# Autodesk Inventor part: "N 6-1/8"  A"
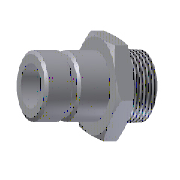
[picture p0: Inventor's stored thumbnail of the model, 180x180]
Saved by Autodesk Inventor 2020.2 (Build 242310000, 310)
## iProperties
IsCustomPart: 1
Manager: www.cadconsulting.pl
Company: Fabian Stasiak CAD Consulting
Created: 2014-02
Part Number: "N 6-1/8"  A"
Material: Copper,Cu
Description: Connector Plug
Document SubType Name: Modeling
Designer: F.Stasiak
Standard Revision: 1
Manufacturer: DME
Language: pl-PL
Size Designation: "N 6-1/8"  A"
Categories: <MemberInstance><Categories><Category DisplayName="Forma wtryskowa" InternalName="349578f2-f4d4-4954-8c09-8e99297a61c0" Mnemonic="MOLD"><Category DisplayName="K
Mass: 1.2815 g
Surface Area: 14.3289 cm^2
Volume: 1.2815 cm^3
Density: 8.96 g/cm^3
Appearance: Domyślne
Catalog Web Link: www.expertbooks.pl
Author: F.Stasiak
Subject: Zbiór ćwiczeń. Autodesk Inventor 2020. Kurs Professional
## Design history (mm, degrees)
sketch "Sketch1"
  geometry: L1 (0, -8.77)-(0, 24.83) reference; L2 (36.525, 1.418)-(37.025, 17.418); L3 (37.025, 17.418)-(36.525, 17.418); L4 (36.525, 17.418)-(36.525, 1.418); L5 (4.74, -3.97)-(4.864, 0); L6 (4.74, -3.97)-(3, -3.97); L7 (4.864, 0)-(4.942, 2.5); L8 (3, -3.97)-(3, 20.03); L9 (4.7, 6.4)-(4.7, 20.03); L10 (4.7, 20.03)-(3, 20.03); L11 (4.7, 6.4)-(6.5, 6.4); L12 (4.942, 2.5)-(6.5, 2.5); L13 (6.5, 2.5)-(7.506, 3.081); L14 (7.506, 3.081)-(7.506, 5.819); L15 (7.506, 5.819)-(6.5, 6.4); 1 further point
  constraints: 28 end point, 3 horizontal, 3 vertical, 2 parallel, 2 perpendicular, 1 collinear, 1 equal length, 1 horizontal alignment
  dimensions: "d0" = 0.5 distance of L2.end L3.end (derived); "d2" = 16 distance of L3.end L2.start (derived); "d3" = 9.728 diameter of L5.end L1 (= R_); "d6" = 9.4 diameter of L9 L1 (= d1); "d7" = 6 diameter of L8 L1 (= d); "d10" = 24 distance between parallel lines of L6 L10 (= L); "d51" = 3.97 vertical distance of L5.start L5.end (= a); "d59" = 2.5 distance from line of L5.end L12 (derived); "d60" = 60 deg angle of L14 L15 (derived); "d61" = 60 deg angle of L14 L13 (derived); "d62" = 13 diameter of L11.end L1 (derived); "d63" = 15.01111 diameter of L14 L1 (derived); "d64" = 3.9 distance between parallel lines of L12 L11 (derived)
revolve "Revolution1" sketch "Sketch1" stored, may be unused: angle "d20" = 90 deg
sketch "Sketch2"
  geometry: L1 (0, -4.006)-(0, 24.036) reference; L2 (4.7, 6.4)-(4.7, 20.03) reference; L3 (4.7, 14.578)-(4.2, 14.078); L4 (4.2, 14.078)-(4.2, 13.078); L5 (4.2, 13.078)-(4.7, 12.578); L6 (4.7, 20.03)-(-4.7, 20.03) reference; L7 (4.7, 14.578)-(4.7, 12.578); 1 further point
  constraints: 8 end point, 2 point on line, 1 collinear, 1 perpendicular, 1 vertical
  dimensions: "d24" = 0.5 distance between parallel lines of L2 L4 (derived); "d25" = 2 distance of L5.end L3.start (derived); "d26" = 5.452 distance from line of L6 L3.start (derived); "d27" = 135 deg angle of L4 L3 (derived); "d55" = 13.63 distance of L2.start L2.end (derived)
revolve "Revolution2" sketch "Sketch2" stored, may be unused: angle "d28" = 90 deg
sketch "Sketch3"
  geometry: L1 (-10.508, 0)-(10.508, 0) reference; L2 (7.506, 0)-(3.753, -6.5); L3 (3.753, -6.5)-(-3.753, -6.5); L4 (-3.753, -6.5)-(-7.506, 0); L5 (-7.506, 0)-(-3.753, 6.5); L6 (-3.753, 6.5)-(3.753, 6.5); L7 (3.753, 6.5)-(7.506, 0); 2 further points
  constraints: 12 end point, 1 coincident, 1 point on line, 13 other
  dimensions: "d65" = 13 distance between parallel lines of L4 L7 (derived)
extrude "Extrusion1" sketch "Sketch3" extent not by distance; stored distance "d66" = 10; taper "d67" = 0 deg
thread "Thread1" dims "d29" = 10, "d30" = 0
chamfer "Chamfer1" distance "d36" = 0.5; stored, may be unused: second distance "d37" = 2, angle "d38" = 45 deg
body "Solid1"
other parameters: "R_" = 9.728 [user parameter; used in 1 equation term], "d1" = 9.4 [user parameter; used in 1 equation term], "d" = 6 [user parameter; used in 1 equation term], "L" = 24 [user parameter; used in 1 equation term], "SW" = 13 [user parameter], "A_" = 22 [user parameter], "B" = 18 [user parameter], "H_" = 17 [user parameter], "a" = 3.97 [user parameter; used in 1 equation term], "f_" = 2.5 [user parameter], "d53" = 0, "d68" = 0, "d69" = 2.5 (derived), "d100" = 0.5 [user parameter], "d101" = 16 [user parameter], "d102" = 2 [user parameter], "d103" = 135 deg [user parameter], "d104" = 60 deg [user parameter], "L2" = 6.47 [user parameter], "L1" = 13.63 [user parameter]
